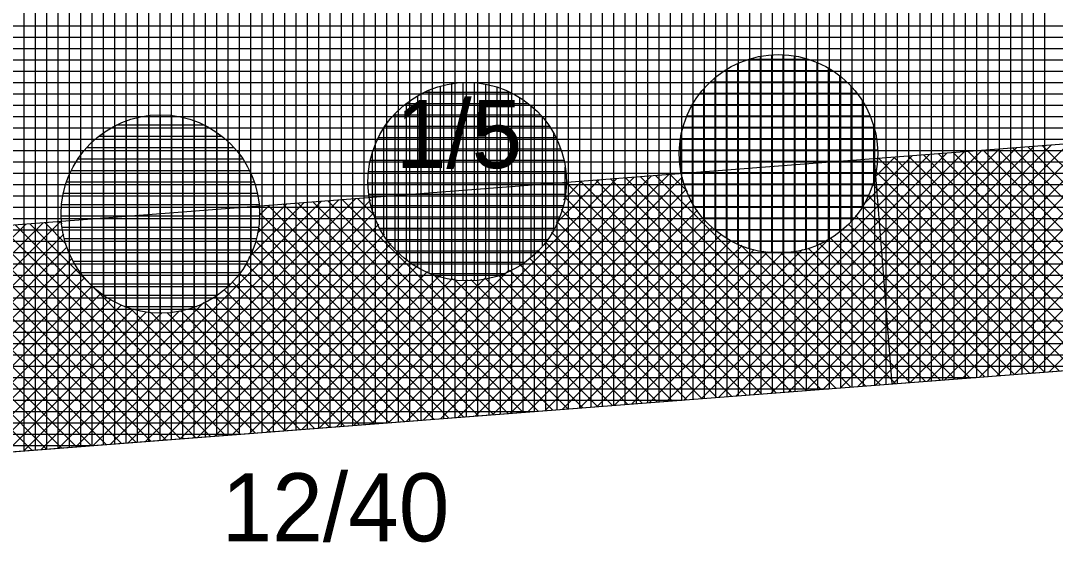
# Model space of a CAD drawing. Extents: x -566461 to -565198, y -1096301 to -1095707.
# Drawn here: x -566336.54 to -566318.3, y -1095862.78 to -1095853.58 of the extents above; entities that cross this region are included whole.
import ezdxf

# ---------------------------------------------------------------- set-up
doc = ezdxf.new("R2010")
doc.units = 0
for name, color, linetype in [('Vrstva 1', 7, 'Continuous'), ('Vrstva 40', 7, 'Continuous'), ('Vrstva 41', 7, 'Continuous'), ('Vrstva 42', 7, 'Continuous'), ('Vrstva 43', 7, 'Continuous'), ('Vrstva 44', 7, 'Continuous')]:
    doc.layers.add(name, color=color, linetype=linetype)

msp = doc.modelspace()

# ---------------------------------------------------------------- linework, layer by layer
at = {"layer": 'Vrstva 1'}
msp.add_line((-566351.09, -1095862.29), (-566300.24, -1095858.37), dxfattribs=at)
at = {"layer": 'Vrstva 41'}
for p, q in [((-566319.905, -1095855.893), (-566324.231, -1095860.219)), ((-566319.598, -1095855.869), (-566323.925, -1095860.196)), ((-566319.292, -1095855.845), (-566323.618, -1095860.172)), ((-566318.985, -1095855.822), (-566323.312, -1095860.149)), ((-566318.679, -1095855.798), (-566323.006, -1095860.125)), ((-566318.372, -1095855.774), (-566322.699, -1095860.101)), ((-566318.105, -1095855.79), (-566322.393, -1095860.078)), ((-566319.836, -1095855.887), (-566316.129, -1095859.595)), ((-566319.574, -1095855.867), (-566315.866, -1095859.575)), ((-566319.311, -1095855.847), (-566315.604, -1095859.554)), ((-566319.049, -1095855.827), (-566315.341, -1095859.534)), ((-566318.786, -1095855.806), (-566315.079, -1095859.514)), ((-566318.523, -1095855.786), (-566317.905, -1095856.404)), ((-566320.517, -1095855.94), (-566324.844, -1095860.267)), ((-566320.211, -1095855.916), (-566324.538, -1095860.243)), ((-566318.057, -1095856.025), (-566322.086, -1095860.054)), ((-566320.824, -1095855.963), (-566321.696, -1095856.836)), ((-566321.13, -1095855.987), (-566321.494, -1095856.35)), ((-566321.437, -1095856.011), (-566321.45, -1095856.024)), ((-566321.412, -1095856.009), (-566317.705, -1095859.716)), ((-566321.149, -1095855.989), (-566317.442, -1095859.696)), ((-566320.887, -1095855.968), (-566317.179, -1095859.676)), ((-566320.624, -1095855.948), (-566316.917, -1095859.656)), ((-566320.362, -1095855.928), (-566316.654, -1095859.635)), ((-566320.099, -1095855.908), (-566316.392, -1095859.615)), ((-566317.986, -1095856.237), (-566321.78, -1095860.03)), ((-566321.472, -1095856.232), (-566317.967, -1095859.737)), ((-566326.034, -1095856.365), (-566330.361, -1095860.692)), ((-566325.727, -1095856.341), (-566330.054, -1095860.668)), ((-566325.421, -1095856.318), (-566329.748, -1095860.645)), ((-566325.114, -1095856.294), (-566329.441, -1095860.621)), ((-566324.871, -1095856.334), (-566329.135, -1095860.597)), ((-566326.34, -1095856.389), (-566327.103, -1095857.151)), ((-566326.647, -1095856.412), (-566326.973, -1095856.738)), ((-566326.927, -1095856.434), (-566323.219, -1095860.141)), ((-566326.664, -1095856.414), (-566322.957, -1095860.121)), ((-566326.401, -1095856.393), (-566322.694, -1095860.101)), ((-566326.139, -1095856.373), (-566322.431, -1095860.081)), ((-566325.876, -1095856.353), (-566322.169, -1095860.06)), ((-566325.614, -1095856.333), (-566321.906, -1095860.04)), ((-566325.351, -1095856.312), (-566321.644, -1095860.02)), ((-566325.088, -1095856.292), (-566324.787, -1095856.594)), ((-566317.894, -1095856.427), (-566321.473, -1095860.007)), ((-566324.804, -1095856.549), (-566328.828, -1095860.574)), ((-566321.524, -1095856.463), (-566318.23, -1095859.757)), ((-566317.783, -1095856.599), (-566321.167, -1095859.983)), ((-566331.244, -1095856.767), (-566335.571, -1095861.094)), ((-566330.937, -1095856.743), (-566335.264, -1095861.07)), ((-566330.631, -1095856.719), (-566334.958, -1095861.046)), ((-566330.369, -1095856.741), (-566334.651, -1095861.023)), ((-566331.55, -1095856.79), (-566332.519, -1095857.759)), ((-566331.654, -1095856.798), (-566327.946, -1095860.506)), ((-566331.391, -1095856.778), (-566327.683, -1095860.486)), ((-566331.128, -1095856.758), (-566327.421, -1095860.465)), ((-566330.866, -1095856.737), (-566327.158, -1095860.445)), ((-566330.603, -1095856.717), (-566330.285, -1095857.035)), ((-566324.716, -1095856.744), (-566328.522, -1095860.55)), ((-566326.966, -1095856.677), (-566323.482, -1095860.162)), ((-566321.604, -1095856.665), (-566318.492, -1095859.777)), ((-566317.654, -1095856.754), (-566320.86, -1095859.96)), ((-566330.312, -1095856.966), (-566334.345, -1095860.999)), ((-566331.857, -1095856.814), (-566332.374, -1095857.331)), ((-566332.163, -1095856.838), (-566332.341, -1095857.015)), ((-566332.339, -1095856.961), (-566328.734, -1095860.567)), ((-566332.179, -1095856.839), (-566328.471, -1095860.546)), ((-566331.916, -1095856.818), (-566328.208, -1095860.526)), ((-566324.609, -1095856.92), (-566328.215, -1095860.527)), ((-566327.013, -1095856.913), (-566323.744, -1095860.182)), ((-566321.704, -1095856.848), (-566318.755, -1095859.797)), ((-566317.51, -1095856.892), (-566320.554, -1095859.936)), ((-566336.454, -1095857.168), (-566340.781, -1095861.495)), ((-566336.147, -1095857.145), (-566340.474, -1095861.472)), ((-566335.841, -1095857.121), (-566340.168, -1095861.448)), ((-566336.38, -1095857.163), (-566332.673, -1095860.87)), ((-566336.118, -1095857.142), (-566335.739, -1095857.521)), ((-566335.855, -1095857.122), (-566335.813, -1095857.164)), ((-566330.229, -1095857.166), (-566334.038, -1095860.975)), ((-566324.485, -1095857.079), (-566327.909, -1095860.503)), ((-566327.088, -1095857.121), (-566324.007, -1095860.202)), ((-566321.955, -1095857.162), (-566319.28, -1095859.838)), ((-566321.821, -1095857.014), (-566319.018, -1095859.818)), ((-566317.348, -1095857.013), (-566320.247, -1095859.912)), ((-566317.17, -1095857.118), (-566319.941, -1095859.889)), ((-566335.785, -1095857.348), (-566339.861, -1095861.424)), ((-566337.956, -1095857.284), (-566334.248, -1095860.992)), ((-566337.693, -1095857.264), (-566333.986, -1095860.971)), ((-566337.431, -1095857.244), (-566333.723, -1095860.951)), ((-566337.168, -1095857.223), (-566333.46, -1095860.931)), ((-566336.906, -1095857.203), (-566333.198, -1095860.911)), ((-566336.643, -1095857.183), (-566332.935, -1095860.89)), ((-566330.128, -1095857.348), (-566333.732, -1095860.952)), ((-566332.362, -1095857.221), (-566328.996, -1095860.587)), ((-566324.345, -1095857.222), (-566327.603, -1095860.479)), ((-566324.188, -1095857.348), (-566327.296, -1095860.456)), ((-566327.185, -1095857.307), (-566324.27, -1095860.222)), ((-566322.105, -1095857.296), (-566319.543, -1095859.858)), ((-566316.973, -1095857.204), (-566319.634, -1095859.865)), ((-566316.755, -1095857.269), (-566319.328, -1095859.841)), ((-566316.507, -1095857.304), (-566319.021, -1095859.818)), ((-566316.223, -1095857.302), (-566318.715, -1095859.794)), ((-566315.871, -1095857.233), (-566318.409, -1095859.771)), ((-566330.009, -1095857.512), (-566333.425, -1095860.928)), ((-566332.405, -1095857.461), (-566329.259, -1095860.607)), ((-566327.3, -1095857.474), (-566324.532, -1095860.243)), ((-566324.013, -1095857.456), (-566326.99, -1095860.432)), ((-566322.274, -1095857.414), (-566325.151, -1095860.29)), ((-566323.844, -1095857.537), (-566321.381, -1095860)), ((-566322.455, -1095857.511), (-566320.068, -1095859.899)), ((-566322.272, -1095857.412), (-566319.805, -1095859.878)), ((-566335.722, -1095857.568), (-566339.555, -1095861.401)), ((-566337.955, -1095857.568), (-566334.511, -1095861.012)), ((-566329.874, -1095857.66), (-566333.119, -1095860.905)), ((-566332.477, -1095857.671), (-566329.521, -1095860.627)), ((-566327.432, -1095857.626), (-566324.795, -1095860.263)), ((-566323.82, -1095857.546), (-566326.683, -1095860.408)), ((-566323.607, -1095857.615), (-566326.377, -1095860.385)), ((-566323.368, -1095857.659), (-566326.07, -1095860.361)), ((-566323.091, -1095857.665), (-566325.764, -1095860.338)), ((-566322.76, -1095857.616), (-566325.457, -1095860.314)), ((-566323.452, -1095857.646), (-566321.118, -1095859.979)), ((-566323.147, -1095857.668), (-566320.856, -1095859.959)), ((-566322.889, -1095857.643), (-566320.593, -1095859.939)), ((-566322.66, -1095857.59), (-566320.331, -1095859.919)), ((-566335.638, -1095857.766), (-566339.248, -1095861.377)), ((-566337.967, -1095857.839), (-566334.773, -1095861.032)), ((-566329.723, -1095857.791), (-566332.813, -1095860.881)), ((-566332.571, -1095857.861), (-566329.784, -1095860.648)), ((-566327.744, -1095857.879), (-566325.32, -1095860.303)), ((-566327.58, -1095857.761), (-566325.057, -1095860.283)), ((-566335.534, -1095857.946), (-566338.942, -1095861.354)), ((-566332.684, -1095858.031), (-566330.047, -1095860.668)), ((-566329.555, -1095857.906), (-566332.506, -1095860.857)), ((-566329.369, -1095858.003), (-566332.2, -1095860.834)), ((-566329.161, -1095858.078), (-566331.893, -1095860.81)), ((-566327.939, -1095857.987), (-566330.667, -1095860.716)), ((-566329.285, -1095858.035), (-566326.896, -1095860.425)), ((-566328.126, -1095858.063), (-566325.845, -1095860.344)), ((-566327.926, -1095857.98), (-566325.583, -1095860.324)), ((-566335.414, -1095858.108), (-566338.635, -1095861.33)), ((-566335.277, -1095858.254), (-566338.329, -1095861.306)), ((-566338.002, -1095858.087), (-566335.036, -1095861.052)), ((-566332.813, -1095858.184), (-566330.309, -1095860.688)), ((-566328.929, -1095858.129), (-566331.587, -1095860.786)), ((-566328.667, -1095858.15), (-566331.28, -1095860.763)), ((-566328.354, -1095858.12), (-566330.974, -1095860.739)), ((-566328.905, -1095858.133), (-566326.633, -1095860.405)), ((-566328.608, -1095858.147), (-566326.37, -1095860.384)), ((-566328.352, -1095858.12), (-566326.108, -1095860.364)), ((-566338.07, -1095858.302), (-566335.299, -1095861.073)), ((-566335.124, -1095858.384), (-566338.022, -1095861.283)), ((-566333.121, -1095858.442), (-566330.834, -1095860.729)), ((-566332.959, -1095858.321), (-566330.572, -1095860.708)), ((-566338.159, -1095858.495), (-566335.561, -1095861.093)), ((-566334.954, -1095858.497), (-566337.716, -1095861.259)), ((-566334.765, -1095858.591), (-566337.41, -1095861.235)), ((-566333.311, -1095858.551), (-566335.877, -1095861.117)), ((-566333.498, -1095858.63), (-566331.36, -1095860.769)), ((-566333.3, -1095858.546), (-566331.097, -1095860.749)), ((-566338.266, -1095858.671), (-566335.824, -1095861.113)), ((-566334.555, -1095858.664), (-566337.103, -1095861.212)), ((-566334.322, -1095858.713), (-566336.797, -1095861.188)), ((-566334.056, -1095858.731), (-566336.49, -1095861.165)), ((-566333.74, -1095858.698), (-566336.184, -1095861.141)), ((-566334.611, -1095858.649), (-566332.41, -1095860.85)), ((-566334.254, -1095858.723), (-566332.147, -1095860.83)), ((-566333.968, -1095858.726), (-566331.885, -1095860.809)), ((-566333.718, -1095858.694), (-566331.622, -1095860.789)), ((-566338.533, -1095858.97), (-566336.349, -1095861.154)), ((-566338.391, -1095858.829), (-566336.086, -1095861.133))]:
    msp.add_line(p, q, dxfattribs=at)
at = {"layer": 'Vrstva 42'}
msp.add_line((-566321.179, -1095859.984), (-566321.485, -1095856.014), dxfattribs=at)
msp.add_lwpolyline([(-566351.98, -1095858.365), (-566351.09, -1095862.29), (-566300.24, -1095858.37), (-566301.163, -1095854.448)], close=True, dxfattribs=at)
at = {"layer": 'Vrstva 43'}
for p, q in [((-566318.49, -1095838.557), (-566318.49, -1095859.777)), ((-566320.29, -1095838.733), (-566320.29, -1095859.916)), ((-566320.09, -1095838.714), (-566320.09, -1095859.9)), ((-566319.89, -1095838.694), (-566319.89, -1095859.885)), ((-566319.69, -1095838.675), (-566319.69, -1095859.869)), ((-566319.49, -1095838.655), (-566319.49, -1095859.854)), ((-566319.29, -1095838.635), (-566319.29, -1095859.839)), ((-566319.09, -1095838.616), (-566319.09, -1095859.823)), ((-566318.89, -1095838.596), (-566318.89, -1095859.808)), ((-566318.69, -1095838.577), (-566318.69, -1095859.792)), ((-566322.29, -1095838.929), (-566322.29, -1095860.07)), ((-566322.09, -1095838.909), (-566322.09, -1095860.054)), ((-566321.89, -1095838.89), (-566321.89, -1095860.039)), ((-566321.69, -1095838.87), (-566321.69, -1095860.024)), ((-566321.49, -1095838.851), (-566321.49, -1095860.008)), ((-566321.29, -1095838.831), (-566321.29, -1095859.993)), ((-566321.09, -1095838.811), (-566321.09, -1095859.977)), ((-566320.89, -1095838.792), (-566320.89, -1095859.962)), ((-566320.69, -1095838.772), (-566320.69, -1095859.946)), ((-566320.49, -1095838.753), (-566320.49, -1095859.931)), ((-566324.09, -1095839.105), (-566324.09, -1095860.209)), ((-566323.89, -1095839.085), (-566323.89, -1095860.193)), ((-566323.69, -1095839.066), (-566323.69, -1095860.178)), ((-566323.49, -1095839.046), (-566323.49, -1095860.162)), ((-566323.29, -1095839.027), (-566323.29, -1095860.147)), ((-566323.09, -1095839.007), (-566323.09, -1095860.131)), ((-566322.89, -1095838.987), (-566322.89, -1095860.116)), ((-566322.69, -1095838.968), (-566322.69, -1095860.101)), ((-566322.49, -1095838.948), (-566322.49, -1095860.085)), ((-566325.89, -1095839.281), (-566325.89, -1095860.347)), ((-566325.69, -1095839.261), (-566325.69, -1095860.332)), ((-566325.49, -1095839.242), (-566325.49, -1095860.317)), ((-566325.29, -1095839.222), (-566325.29, -1095860.301)), ((-566325.09, -1095839.202), (-566325.09, -1095860.286)), ((-566324.89, -1095839.183), (-566324.89, -1095860.27)), ((-566324.69, -1095839.163), (-566324.69, -1095860.255)), ((-566324.49, -1095839.144), (-566324.49, -1095860.239)), ((-566324.29, -1095839.124), (-566324.29, -1095860.224)), ((-566327.89, -1095839.476), (-566327.89, -1095860.502)), ((-566327.69, -1095839.457), (-566327.69, -1095860.486)), ((-566327.49, -1095839.437), (-566327.49, -1095860.471)), ((-566327.29, -1095839.418), (-566327.29, -1095860.455)), ((-566327.09, -1095839.398), (-566327.09, -1095860.44)), ((-566326.89, -1095839.378), (-566326.89, -1095860.424)), ((-566326.69, -1095839.359), (-566326.69, -1095860.409)), ((-566326.49, -1095839.339), (-566326.49, -1095860.394)), ((-566326.29, -1095839.32), (-566326.29, -1095860.378)), ((-566326.09, -1095839.3), (-566326.09, -1095860.363)), ((-566329.69, -1095839.652), (-566329.69, -1095860.64)), ((-566329.49, -1095839.633), (-566329.49, -1095860.625)), ((-566329.29, -1095839.613), (-566329.29, -1095860.609)), ((-566329.09, -1095839.594), (-566329.09, -1095860.594)), ((-566328.89, -1095839.574), (-566328.89, -1095860.579)), ((-566328.69, -1095839.554), (-566328.69, -1095860.563)), ((-566328.49, -1095839.535), (-566328.49, -1095860.548)), ((-566328.29, -1095839.515), (-566328.29, -1095860.532)), ((-566328.09, -1095839.496), (-566328.09, -1095860.517)), ((-566331.49, -1095839.828), (-566331.49, -1095860.779)), ((-566331.29, -1095839.809), (-566331.29, -1095860.764)), ((-566331.09, -1095839.789), (-566331.09, -1095860.748)), ((-566330.89, -1095839.769), (-566330.89, -1095860.733)), ((-566330.69, -1095839.75), (-566330.69, -1095860.717)), ((-566330.49, -1095839.73), (-566330.49, -1095860.702)), ((-566330.29, -1095839.711), (-566330.29, -1095860.687)), ((-566330.09, -1095839.691), (-566330.09, -1095860.671)), ((-566329.89, -1095839.672), (-566329.89, -1095860.656)), ((-566333.49, -1095840.024), (-566333.49, -1095860.933)), ((-566333.29, -1095840.004), (-566333.29, -1095860.918)), ((-566333.09, -1095839.985), (-566333.09, -1095860.902)), ((-566332.89, -1095839.965), (-566332.89, -1095860.887)), ((-566332.69, -1095839.945), (-566332.69, -1095860.872)), ((-566332.49, -1095839.926), (-566332.49, -1095860.856)), ((-566332.29, -1095839.906), (-566332.29, -1095860.841)), ((-566332.09, -1095839.887), (-566332.09, -1095860.825)), ((-566331.89, -1095839.867), (-566331.89, -1095860.81)), ((-566331.69, -1095839.848), (-566331.69, -1095860.794)), ((-566335.29, -1095840.2), (-566335.29, -1095861.072)), ((-566335.09, -1095840.18), (-566335.09, -1095861.057)), ((-566334.89, -1095840.161), (-566334.89, -1095861.041)), ((-566334.69, -1095840.141), (-566334.69, -1095861.026)), ((-566334.49, -1095840.121), (-566334.49, -1095861.01)), ((-566334.29, -1095840.102), (-566334.29, -1095860.995)), ((-566334.09, -1095840.082), (-566334.09, -1095860.979)), ((-566333.89, -1095840.063), (-566333.89, -1095860.964)), ((-566333.69, -1095840.043), (-566333.69, -1095860.949)), ((-566336.49, -1095840.317), (-566336.49, -1095861.164)), ((-566336.29, -1095840.297), (-566336.29, -1095861.149)), ((-566336.09, -1095840.278), (-566336.09, -1095861.134)), ((-566335.89, -1095840.258), (-566335.89, -1095861.118)), ((-566335.69, -1095840.239), (-566335.69, -1095861.103)), ((-566335.49, -1095840.219), (-566335.49, -1095861.087)), ((-566353.046, -1095853.67), (-566301.349, -1095853.67)), ((-566353, -1095853.87), (-566301.302, -1095853.87)), ((-566352.955, -1095854.07), (-566301.254, -1095854.07)), ((-566352.909, -1095854.27), (-566301.207, -1095854.27)), ((-566352.864, -1095854.47), (-566301.16, -1095854.47)), ((-566352.819, -1095854.67), (-566301.113, -1095854.67)), ((-566352.773, -1095854.87), (-566301.066, -1095854.87)), ((-566352.728, -1095855.07), (-566301.018, -1095855.07)), ((-566352.683, -1095855.27), (-566300.971, -1095855.27)), ((-566352.637, -1095855.47), (-566300.924, -1095855.47)), ((-566352.592, -1095855.67), (-566300.877, -1095855.67)), ((-566352.546, -1095855.87), (-566300.83, -1095855.87)), ((-566352.501, -1095856.07), (-566300.783, -1095856.07)), ((-566352.456, -1095856.27), (-566300.735, -1095856.27)), ((-566352.41, -1095856.47), (-566300.688, -1095856.47)), ((-566352.365, -1095856.67), (-566300.641, -1095856.67)), ((-566352.32, -1095856.87), (-566300.594, -1095856.87)), ((-566352.274, -1095857.07), (-566300.547, -1095857.07)), ((-566352.229, -1095857.27), (-566300.499, -1095857.27)), ((-566352.183, -1095857.47), (-566300.452, -1095857.47)), ((-566352.138, -1095857.67), (-566300.405, -1095857.67)), ((-566352.093, -1095857.87), (-566300.358, -1095857.87)), ((-566352.047, -1095858.07), (-566300.311, -1095858.07)), ((-566352.002, -1095858.27), (-566300.264, -1095858.27)), ((-566351.957, -1095858.47), (-566301.537, -1095858.47)), ((-566351.911, -1095858.67), (-566304.132, -1095858.67)), ((-566351.866, -1095858.87), (-566306.726, -1095858.87)), ((-566351.821, -1095859.07), (-566309.32, -1095859.07)), ((-566351.775, -1095859.27), (-566311.915, -1095859.27)), ((-566351.73, -1095859.47), (-566314.509, -1095859.47)), ((-566351.684, -1095859.67), (-566317.104, -1095859.67)), ((-566351.639, -1095859.87), (-566319.698, -1095859.87)), ((-566351.594, -1095860.07), (-566322.292, -1095860.07)), ((-566351.548, -1095860.27), (-566324.887, -1095860.27)), ((-566351.503, -1095860.47), (-566327.481, -1095860.47)), ((-566351.458, -1095860.67), (-566330.075, -1095860.67)), ((-566351.412, -1095860.87), (-566332.67, -1095860.87)), ((-566351.367, -1095861.07), (-566335.264, -1095861.07))]:
    msp.add_line(p, q, dxfattribs=at)
msp.add_lwpolyline([(-566355.65, -1095842.19), (-566351.09, -1095862.29), (-566300.24, -1095858.37), (-566305.22, -1095837.26)], close=True, dxfattribs=at)
at = {"layer": 'Vrstva 44'}
for p, q in [((-566323.5, -1095857.649), (-566323.5, -1095854.21)), ((-566323.3, -1095857.674), (-566323.3, -1095854.185)), ((-566323.1, -1095857.677), (-566323.1, -1095854.184)), ((-566322.9, -1095857.657), (-566322.9, -1095854.205)), ((-566322.7, -1095857.612), (-566322.7, -1095854.249)), ((-566323.9, -1095857.523), (-566323.9, -1095854.337)), ((-566323.7, -1095857.6), (-566323.7, -1095854.261)), ((-566323.698, -1095854.26), (-566322.658, -1095854.26)), ((-566322.5, -1095857.54), (-566322.5, -1095854.318)), ((-566322.3, -1095857.441), (-566322.3, -1095854.42)), ((-566324.3, -1095857.273), (-566324.3, -1095854.588)), ((-566324.128, -1095854.46), (-566322.232, -1095854.46)), ((-566324.1, -1095857.417), (-566324.1, -1095854.442)), ((-566322.1, -1095857.305), (-566322.1, -1095854.555)), ((-566329.14, -1095858.105), (-566329.14, -1095854.734)), ((-566328.94, -1095858.147), (-566328.94, -1095854.692)), ((-566328.74, -1095858.168), (-566328.74, -1095854.673)), ((-566328.54, -1095858.165), (-566328.54, -1095854.677)), ((-566328.34, -1095858.137), (-566328.34, -1095854.703)), ((-566328.14, -1095858.086), (-566328.14, -1095854.753)), ((-566324.5, -1095857.078), (-566324.5, -1095854.782)), ((-566324.383, -1095854.66), (-566321.978, -1095854.66)), ((-566321.9, -1095857.122), (-566321.9, -1095854.74)), ((-566329.54, -1095857.936), (-566329.54, -1095854.904)), ((-566329.419, -1095854.84), (-566327.922, -1095854.84)), ((-566329.34, -1095858.036), (-566329.34, -1095854.805)), ((-566327.94, -1095858.009), (-566327.94, -1095854.832)), ((-566327.74, -1095857.901), (-566327.74, -1095854.939)), ((-566324.563, -1095854.86), (-566321.798, -1095854.86)), ((-566329.745, -1095855.04), (-566327.596, -1095855.04)), ((-566329.74, -1095857.804), (-566329.74, -1095855.035)), ((-566327.54, -1095857.754), (-566327.54, -1095855.085)), ((-566324.7, -1095856.797), (-566324.7, -1095855.065)), ((-566324.697, -1095855.06), (-566321.663, -1095855.06)), ((-566321.7, -1095856.862), (-566321.7, -1095855)), ((-566334.68, -1095858.632), (-566334.68, -1095855.347)), ((-566334.48, -1095858.693), (-566334.48, -1095855.288)), ((-566334.28, -1095858.728), (-566334.28, -1095855.253)), ((-566334.08, -1095858.738), (-566334.08, -1095855.241)), ((-566333.88, -1095858.727), (-566333.88, -1095855.252)), ((-566333.68, -1095858.692), (-566333.68, -1095855.288)), ((-566333.48, -1095858.634), (-566333.48, -1095855.348)), ((-566329.961, -1095855.24), (-566327.38, -1095855.24)), ((-566329.94, -1095857.621), (-566329.94, -1095855.219)), ((-566327.34, -1095857.555), (-566327.34, -1095855.284)), ((-566324.795, -1095855.26), (-566321.565, -1095855.26)), ((-566334.88, -1095858.546), (-566334.88, -1095855.434)), ((-566334.852, -1095855.42), (-566333.311, -1095855.42)), ((-566333.28, -1095858.545), (-566333.28, -1095855.435)), ((-566330.14, -1095857.366), (-566330.14, -1095855.474)), ((-566330.118, -1095855.44), (-566327.221, -1095855.44)), ((-566324.864, -1095855.46), (-566321.496, -1095855.46)), ((-566321.5, -1095856.415), (-566321.5, -1095855.447)), ((-566335.167, -1095855.62), (-566332.993, -1095855.62)), ((-566335.08, -1095858.424), (-566335.08, -1095855.556)), ((-566333.08, -1095858.424), (-566333.08, -1095855.556)), ((-566330.235, -1095855.64), (-566327.106, -1095855.64)), ((-566327.14, -1095857.265), (-566327.14, -1095855.571)), ((-566324.909, -1095855.66), (-566321.453, -1095855.66)), ((-566324.9, -1095856.242), (-566324.9, -1095855.617)), ((-566335.381, -1095855.82), (-566332.781, -1095855.82)), ((-566335.28, -1095858.263), (-566335.28, -1095855.717)), ((-566332.88, -1095858.262), (-566332.88, -1095855.718)), ((-566330.321, -1095855.84), (-566327.021, -1095855.84)), ((-566324.928, -1095855.86), (-566321.432, -1095855.86)), ((-566335.534, -1095856.02), (-566332.625, -1095856.02)), ((-566335.48, -1095858.037), (-566335.48, -1095855.942)), ((-566332.68, -1095858.04), (-566332.68, -1095855.943)), ((-566330.377, -1095856.04), (-566326.962, -1095856.04)), ((-566330.34, -1095856.938), (-566330.34, -1095855.904)), ((-566324.923, -1095856.06), (-566321.435, -1095856.06)), ((-566335.65, -1095856.22), (-566332.511, -1095856.22)), ((-566330.409, -1095856.24), (-566326.931, -1095856.24)), ((-566326.94, -1095856.676), (-566326.94, -1095856.166)), ((-566324.897, -1095856.26), (-566321.463, -1095856.26)), ((-566335.734, -1095856.42), (-566332.427, -1095856.42)), ((-566335.68, -1095857.698), (-566335.68, -1095856.285)), ((-566332.48, -1095857.694), (-566332.48, -1095856.282)), ((-566330.418, -1095856.44), (-566326.922, -1095856.44)), ((-566335.789, -1095856.62), (-566332.37, -1095856.62)), ((-566324.846, -1095856.46), (-566321.514, -1095856.46)), ((-566330.405, -1095856.64), (-566326.936, -1095856.64)), ((-566324.77, -1095856.66), (-566321.591, -1095856.66)), ((-566335.82, -1095856.82), (-566332.34, -1095856.82)), ((-566330.368, -1095856.84), (-566326.972, -1095856.84)), ((-566324.66, -1095856.86), (-566321.699, -1095856.86)), ((-566335.828, -1095857.02), (-566332.332, -1095857.02)), ((-566330.305, -1095857.04), (-566327.034, -1095857.04)), ((-566324.515, -1095857.06), (-566321.846, -1095857.06)), ((-566335.814, -1095857.22), (-566332.347, -1095857.22)), ((-566330.214, -1095857.24), (-566327.126, -1095857.24)), ((-566324.314, -1095857.26), (-566322.045, -1095857.26)), ((-566335.775, -1095857.42), (-566332.385, -1095857.42)), ((-566330.091, -1095857.44), (-566327.25, -1095857.44)), ((-566324.026, -1095857.46), (-566322.335, -1095857.46)), ((-566335.711, -1095857.62), (-566332.448, -1095857.62)), ((-566329.922, -1095857.64), (-566327.418, -1095857.64)), ((-566323.434, -1095857.66), (-566322.924, -1095857.66)), ((-566335.619, -1095857.82), (-566332.542, -1095857.82)), ((-566329.689, -1095857.84), (-566327.649, -1095857.84)), ((-566335.493, -1095858.02), (-566332.666, -1095858.02)), ((-566329.331, -1095858.04), (-566328.013, -1095858.04)), ((-566335.323, -1095858.22), (-566332.838, -1095858.22)), ((-566335.085, -1095858.42), (-566333.074, -1095858.42)), ((-566334.715, -1095858.62), (-566333.446, -1095858.62))]:
    msp.add_line(p, q, dxfattribs=at)
for centre in [(-566323.18, -1095855.93), (-566328.67, -1095856.42), (-566334.08, -1095856.99)]:
    msp.add_circle(centre, 1.75, dxfattribs=at)

# ---------------------------------------------------------------- texts
at = {"layer": 'Vrstva 40'}
for s, p in [('1/5', (-566329.93, -1095856.18)), ('12/40', (-566333, -1095862.76))]:
    msp.add_text(s, height=1.2, dxfattribs=at).set_placement(p)

doc.saveas('drawing.dxf')
